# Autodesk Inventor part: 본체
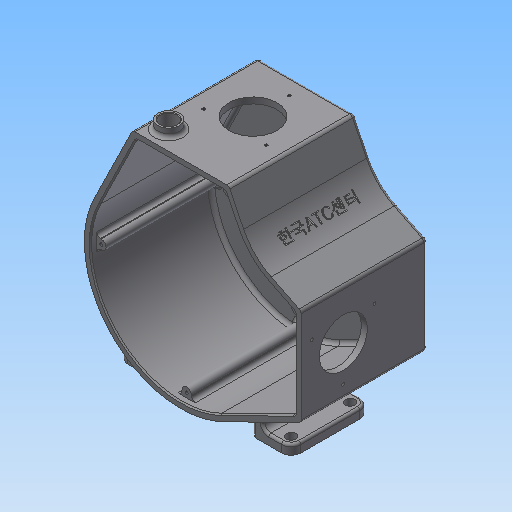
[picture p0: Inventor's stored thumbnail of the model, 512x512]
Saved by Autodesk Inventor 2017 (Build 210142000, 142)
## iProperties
Created: 2017-05
Part Number: 본체
Material: 알루미늄 6061
Document SubType Name: Modeling
Designer: mduedu
Density: 2.71 g/cm^3
Appearance: 기본값
Mass: 1345.72 g
Surface Area: 1824.08 cm^2
Volume: 496.576 cm^3
Author: mduedu
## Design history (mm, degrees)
sketch "스케치1"
  geometry: L1 (-71.801, 35.28)-(-40, 100); L2 (-40, 100)-(40, 100); L3 (40, 100)-(59.768, 59.768); L4 (59.768, 59.768)-(100, 40); L5 (100, 40)-(100, -40); L6 (100, -40)-(35.28, -71.801); A1 r 80 centre (0, 0) between (-71.801, 35.28) and (35.28, -71.801); 3 further points
  constraints: 12 end point, 4 tangent, 2 midpoint, 2 point on circle, 1 centre point, 1 coincident, 1 horizontal, 1 horizontal alignment, 1 perpendicular, 1 vertical alignment
  dimensions: "d0" = 160 diameter of A1; "d2" = 100 distance from line of L2 point (0, 0); "d3" = 100 distance from line of L5 point (0, 0); "d4" = 80 distance of L1.end L2.end; "d5" = 80 distance of L4.end L5.end
extrude "돌출1" new body sketch "스케치1" distance "d6" = 5; taper "d7" = 0 deg
fillet "모깎기1" dims "d8" = 50
sketch "스케치2"
  geometry: C1 r 22 at (0, 0); 1 further point
  constraints: 1 centre point, 1 coincident
  dimensions: "d9" = 44 diameter of C1
extrude "돌출2" join sketch "스케치2" distance "d10" = 22.5; taper "d11" = 0 deg
sketch "스케치3"
  geometry: C1 r 18.5 at (0, 0); 1 further point
  constraints: 1 centre point, 1 coincident
  dimensions: "d12" = 37 diameter of C1
extrude "돌출3" cut sketch "스케치3" distance "d13" = 9; taper "d14" = 0 deg
fillet "모깎기2" dims "d15" = 3
sketch "스케치4"
  geometry: L1 (35.28, -71.801)-(100, -40) reference; L2 (100, -40)-(100, 40) reference; L3 (100, 40)-(75.073, 52.248) reference; L4 (52.248, 75.073)-(40, 100) reference; L5 (40, 100)-(-40, 100) reference; L6 (-40, 100)-(-71.801, 35.28) reference; L7 (-36.886, 95)-(36.886, 95); L8 (36.886, 95)-(47.76, 72.868); L9 (72.868, 47.76)-(95, 36.886); L10 (95, 36.886)-(95, -36.886); L11 (95, -36.886)-(33.075, -67.313); L12 (-67.313, 33.075)-(-36.886, 95); C1 r 25 at (0, 0) reference; A1 r 50 centre (97.123, 97.123) between (52.248, 75.073) and (75.073, 52.248) reference; A2 r 80 centre (0, 0) between (-71.801, 35.28) and (35.28, -71.801) reference; A3 r 55 centre (97.123, 97.123) between (47.76, 72.868) and (72.868, 47.76); A4 r 75 centre (0, 0) between (-67.313, 33.075) and (33.075, -67.313); 1 further point
  constraints: 12 end point, 4 point on circle, 2 centre point, 7 other
  dimensions: "d16" = 5 distance between parallel lines of L7 L5
extrude "돌출4" join sketch "스케치4" distance "d17" = 100; taper "d18" = 0 deg
sketch "스케치5"
  geometry: L1 (80, 0)-(0, 0) reference; C1 r 20 at (40, -45); 2 further points
  constraints: 1 centre point, 1 midpoint, 1 vertical alignment
  dimensions: "d19" = 40 diameter of C1; "d21" = 45 distance from line of C1.centre L1
extrude "돌출5" cut sketch "스케치5" stored distance "d22" = 100; taper "d23" = 0 deg
sketch "스케치6"
  geometry: L1 (0, 0)-(0, -105) reference; L2 (80, -105)-(0, -105) reference; C1 r 9 at (14, -89); 1 further point
  constraints: 1 centre point
  dimensions: "d24" = 18 diameter of C1; "d26" = 14 distance from line of C1.centre L1; "d27" = 16 distance from line of C1.centre L2
extrude "돌출6" join sketch "스케치6" distance "d28" = 7; taper "d29" = 0 deg
hole "구멍1" diameter "d32" = 14; stored, may be unused: countersink angle "d36" = 90 deg, drill point angle "d38" = 118 deg; dims "d33" = 6, "d34" = 4, "d35" = 2, "d37" = 8, "d39" = 10, "d40" = 10
sketch "스케치7"
  geometry: L1 (-105, 0)-(-105, 80) reference; L2 (0, 0)-(0, 80) reference; C1 r 20 at (-70, 40); 2 further points
  constraints: 1 centre point, 1 horizontal alignment, 1 midpoint
  dimensions: "d41" = 40 diameter of C1; "d42" = 35 distance from line of C1.centre L1
extrude "돌출7" cut sketch "스케치7" stored distance "d43" = 7; taper "d44" = 0 deg
node "작업 평면1"
sketch "스케치8"
  geometry: L1 (47.76, 72.868)-(36.886, 95) reference; L2 (36.886, 95)-(-36.886, 95) reference; L3 (-36.886, 95)-(-67.313, 33.075) reference; L4 (33.075, -67.313)-(95, -36.886) reference; L5 (95, -36.886)-(95, 36.886) reference; L6 (95, 36.886)-(72.868, 47.76) reference; L7 (95, 36.886)-(95, -36.886) reference; L8 (-36.886, 95)-(36.886, 95) reference; L9 (36.886, 95)-(47.76, 72.868) reference; L10 (-71, 4)-(-74.893, 4); L11 (-71, -4)-(-74.893, -4); L12 (-4, -71)-(-4, -74.893); L13 (4, -71)-(4, -74.893); L14 (30.394, 91)-(30.394, 95); L15 (34.394, 87)-(40.817, 87); L16 (30.394, 95)-(36.886, 95); L17 (36.886, 95)-(37.984, 92.764); L18 (91, 30.394)-(95, 30.394); L19 (87, 34.394)-(87, 40.817); L20 (87, 40.817)-(95, 36.886); L21 (95, 36.886)-(95, 30.394); C1 r 25 at (0, 0) reference; A1 r 75 centre (0, 0) between (-67.313, 33.075) and (33.075, -67.313) reference; A2 r 55 centre (97.123, 97.123) between (47.76, 72.868) and (72.868, 47.76) reference; A3 r 4 centre (-71, 0) between (-71, 4) and (-71, -4); A4 r 4 centre (0, -71) between (-4, -71) and (4, -71); A5 r 4 centre (34.394, 91) between (30.394, 91) and (34.394, 87); A6 r 75 centre (0, 0) between (-67.313, 33.075) and (33.075, -67.313) reference; A7 r 4 centre (91, 34.394) between (91, 30.394) and (87, 34.394); 1 further point
  constraints: 24 end point, 17 point on circle, 14 tangent, 5 point on line, 4 centre point, 3 equal radius, 3 perpendicular, 3 vertical, 2 collinear, 2 horizontal, 1 horizontal alignment, 1 parallel, 1 vertical alignment
  dimensions: "d46" = 8 diameter of A3
extrude "돌출8" join sketch "스케치8" stored distance "d49" = 7; taper "d50" = 0 deg
node "작업 평면2"
sketch "스케치9"
  geometry: L1 (71.801, 0)-(71.801, 105) reference; L2 (71.801, 0)-(-35.28, 0) reference; L3 (-35.28, 0)-(-35.28, 105) reference; L4 (71.801, 105)-(-35.28, 105) reference; L5 (40, 0)-(40, 105) reference; L6 (71.801, 52.5)-(-35.28, 52.5); L7 (71.801, 20)-(40, 20); L8 (40, 20)-(40, 85); L9 (40, 85)-(71.801, 85); L10 (71.801, 85)-(71.801, 20); 1 further point
  constraints: 10 end point, 2 midpoint, 2 parallel, 2 point on line, 1 horizontal, 1 perpendicular, 1 other
  dimensions: "d52" = 20 distance between parallel lines of L7 L2
extrude "돌출9" join sketch "스케치9" distance "d53" = 8; taper "d54" = 0 deg
fillet "모깎기3" dims "d55" = 8
sketch "스케치10"
  geometry: C1 r 4 at (-63.801, -28); C2 r 4 at (-63.801, -77); A1 r 8 centre (-63.801, -28) between (-63.801, -20) and (-71.801, -28) reference; A2 r 8 centre (-63.801, -77) between (-71.801, -77) and (-63.801, -85) reference; 1 further point
  constraints: 2 centre point, 2 coincident, 1 equal radius
  dimensions: "d56" = 8 diameter of C1
extrude "돌출10" cut sketch "스케치10" stored distance "d57" = 50.5; taper "d58" = 0 deg
sketch "스케치11"
  geometry: L1 (-63.801, -20)-(-40, -20) reference; L2 (-40, -20)-(-40, -85) reference; L3 (-40, -85)-(-63.801, -85) reference; L4 (-71.801, -77)-(-71.801, -28) reference; L5 (71.801, -77)-(71.801, -28) reference; L6 (40, -85)-(63.801, -85) reference; L7 (40, -20)-(40, -85) reference; L8 (63.801, -20)-(40, -20) reference; L9 (-40, -85)-(-48, -85); L10 (-48, -85)-(-48, -20); L11 (-48, -20)-(-40, -20); L12 (-40, -20)-(-40, -85); L13 (40, -85)-(48, -85); L14 (48, -85)-(48, -20); L15 (48, -20)-(40, -20); L16 (40, -20)-(40, -85); C1 r 4 at (-63.801, -28) reference; C2 r 4 at (-63.801, -77) reference; C3 r 4 at (63.801, -28) reference; C4 r 4 at (63.801, -77) reference; A1 r 8 centre (-63.801, -28) between (-63.801, -20) and (-71.801, -28) reference; A2 r 8 centre (-63.801, -77) between (-71.801, -77) and (-63.801, -85) reference; A3 r 8 centre (63.801, -28) between (71.801, -28) and (63.801, -20) reference; A4 r 8 centre (63.801, -77) between (63.801, -85) and (71.801, -77) reference; 1 further point
  constraints: 16 end point, 4 parallel, 2 horizontal, 2 perpendicular, 2 point on line
  dimensions: "d59" = 8 distance of L10.end L11.end; "d61" = 8 distance of L14.end L15.end
extrude "돌출11" join sketch "스케치11" stored distance "d62" = 5; taper "d63" = 0 deg
fillet "모깎기4" dims "d64" = 5
fillet "모깎기5" dims "d65" = 2
fillet "모깎기6" dims "d66" = 2
fillet "모깎기8" dims "d68" = 2
fillet "모깎기9" dims "d70" = 3, "d101" = 1
fillet "모깎기10" dims "d71" = 3
fillet "모깎기11" dims "d72" = 3
fillet "모깎기12" dims "d73" = 3
fillet "모깎기13" dims "d76" = 3
chamfer "모따기1" distance "d77" = 0.5; stored, may be unused: second distance "d78" = 2, angle "d79" = 45 deg
chamfer "모따기2" distance "d87" = 1; stored, may be unused: second distance "d88" = 2, angle "d89" = 45 deg
chamfer "모따기3" distance "d90" = 1; stored, may be unused: second distance "d91" = 2, angle "d92" = 45 deg
sketch "스케치14"
  geometry: 3 further points
  constraints: 3 other
hole "구멍2" sketch "스케치14" at (-55.375, -40), (-3.414, -40), (-29.394, -85) diameter "d93" = 2.459; stored, may be unused: countersink angle "d97" = 90 deg, drill point angle "d99" = 0 deg; dims "d94" = 6, "d95" = 4, "d96" = 2, "d98" = 8
sketch "스케치15"
  geometry: 3 further points
  constraints: 3 other
hole "구멍4" sketch "스케치15" at (-55.981, -14.394), (-4.019, -14.394), (-30, -59.394) diameter "d102" = 2.459; stored, may be unused: countersink angle "d106" = 90 deg, drill point angle "d108" = 0 deg; dims "d103" = 6, "d104" = 4, "d105" = 2, "d107" = 8
sketch "스케치16"
  geometry: 4 further points
  constraints: 4 other
hole "구멍6" sketch "스케치16" at (0, -71), (91, 34.394), (34.394, 91), (-71, 0) diameter "d109" = 2.459; stored, may be unused: countersink angle "d113" = 90 deg, drill point angle "d115" = 120 deg; dims "d110" = 8.5, "d111" = 4, "d112" = 2, "d114" = 10
node "작업 평면4"
sketch "스케치17"
  geometry: 2 further points
  constraints: 1 horizontal alignment, 1 other
  dimensions: "d116" = 52.5 distance of point (0, 16.14) point (52.5, 16.14)
feature "엠보싱2" sketch "스케치17" dims "d117" = 0.5, "d118" = 0
node "솔리드1"
mirror "대칭1"
node "투영된 루프1"
node "투영된 루프2"
node "투영된 루프3"
node "투영된 루프4"
node "투영된 루프5"
other parameters: "d45" = 95
